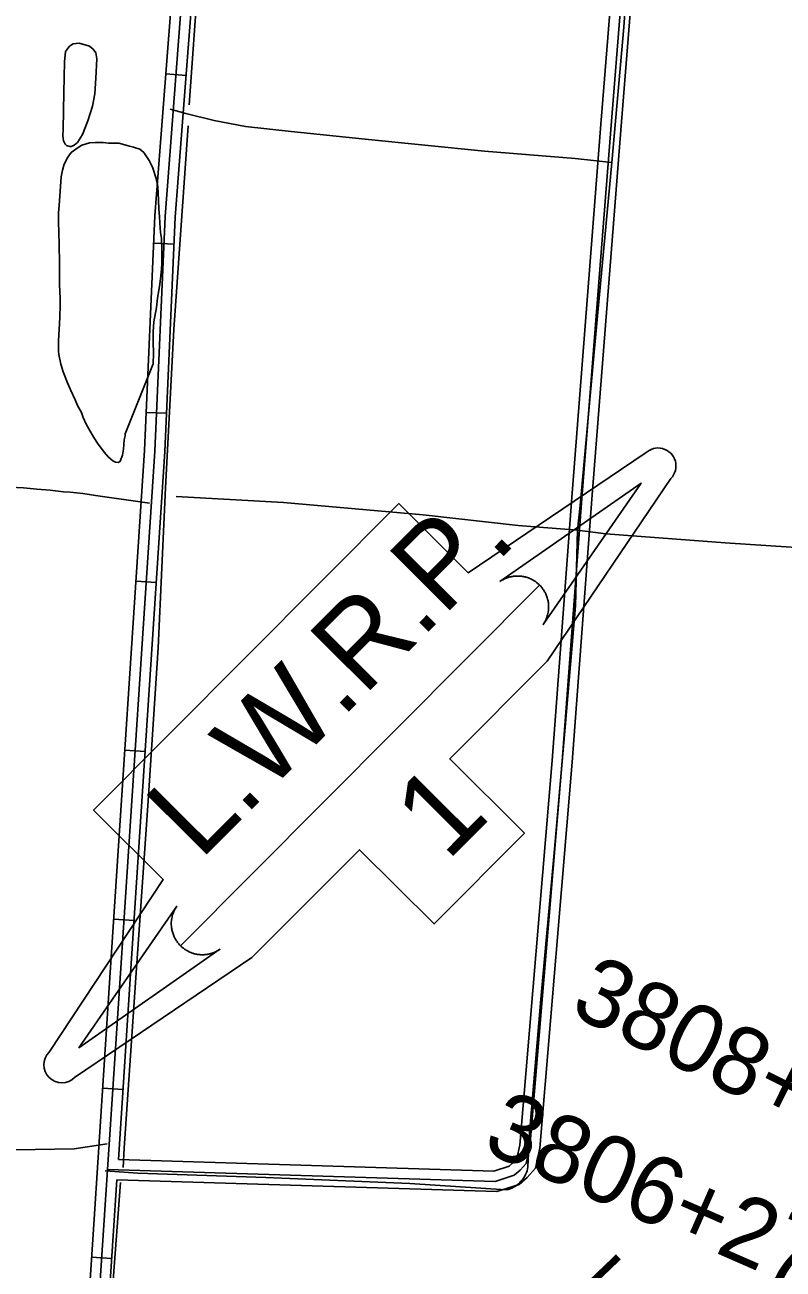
# Model space of a CAD drawing. Extents: x 3419139 to 3457078, y 540382 to 565875.
# Drawn here: x 3450003 to 3451122, y 549375 to 551211 of the extents above; entities that cross this region are included whole.
import ezdxf

# ---------------------------------------------------------------- set-up
doc = ezdxf.new("R2010")
doc.units = 0
for name, color, linetype in [('V-DTCH-CNTR', 7, 'Continuous'), ('V-RIVR-RANG-IDEN', 7, 'Continuous'), ('V-ROAD-CNTR', 7, 'Continuous'), ('V-SITE-VEGE', 7, 'Continuous'), ('V-SURV-IDEN', 7, 'Continuous'), ('V-TOPO-SHOR', 7, 'Continuous'), ('V-TOPO-WATR-IDEN', 7, 'Continuous')]:
    doc.layers.add(name, color=color, linetype=linetype)

msp = doc.modelspace()

# ---------------------------------------------------------------- linework, layer by layer
at = {"layer": 'V-DTCH-CNTR'}
for p, q in [((3450815.2, 551014.2), (3450869.2, 551008.3)), ((3450186.7, 550505.4), (3450107.2, 550516.6)), ((3450822.3, 550501.9), (3450818.5, 550465.6)), ((3450860.2, 550460.1), (3450818.5, 550465.6)), ((3450124.4, 549559.9), (3450075.5, 549552.1))]:
    msp.add_line(p, q, dxfattribs=at)
for points in [[(3450947.1, 551980.6), (3450930.6, 551824.6), (3450911.7, 551558), (3450886.9, 551208.2), (3450869.2, 551008.3)], [(3450217.6, 551087.1), (3450240.4, 551080.9), (3450282.3, 551070.4), (3450328.7, 551061.5), (3450396.2, 551053.9), (3450505.1, 551042.9), (3450681.5, 551025), (3450815.2, 551014.2)], [(3450869.2, 551008.3), (3450847.6, 550776.8), (3450828.9, 550572.3), (3450822.3, 550501.9)], [(3448834, 550578.8), (3449002.2, 550569.4), (3449267.6, 550554.5), (3449513.3, 550542.3), (3449732, 550531.6), (3449878.5, 550528.9), (3449888.8, 550529.8), (3449899.1, 550530.6), (3449909.4, 550531.1), (3449919.8, 550531.4), (3449930.1, 550531.4), (3449940.4, 550531.3), (3449950.7, 550530.9), (3449961, 550530.4), (3449980.9, 550529.3), (3450000.8, 550527.9), (3450020.6, 550526.3), (3450040.4, 550524.5), (3450060.2, 550522.4), (3450069.6, 550521.8), (3450079.1, 550520.9), (3450088.5, 550519.7), (3450097.9, 550518.3), (3450107.2, 550516.6)], [(3450818.5, 550465.6), (3450731.1, 550472.3), (3450590.8, 550488.3), (3450384.4, 550506.2), (3450226, 550515.4)], [(3450818.5, 550465.6), (3450815.6, 550353.7), (3450800.5, 550174.7), (3450784.7, 549994.5), (3450764.6, 549773.5), (3450747.6, 549575.5), (3450745.4, 549525.7)], [(3450860.2, 550460.1), (3451036.4, 550447), (3451193.8, 550436.4), (3451396.4, 550421.6), (3451557, 550407.1), (3451733.7, 550392.4), (3451936.6, 550376.9), (3452074.6, 550364.4), (3452246.1, 550345.2), (3452364.9, 550332.1)], [(3450075.5, 549552.1), (3449931.5, 549550.1), (3449720.3, 549554.1), (3449493.6, 549564), (3449287, 549571.2), (3449106.1, 549576.9), (3448895.9, 549584.8), (3448770, 549590.3)], [(3450745.4, 549525.7), (3450744.9, 549522.8), (3450744.1, 549520), (3450743.1, 549517.3), (3450742, 549514.6), (3450740.6, 549512), (3450739.1, 549509.5), (3450737.4, 549507.1), (3450735.6, 549504.9), (3450733.6, 549502.7), (3450731.5, 549500.7), (3450729.2, 549498.9), (3450726.8, 549497.3), (3450724.3, 549495.8), (3450721.7, 549494.4), (3450719, 549493.3), (3450716.3, 549492.4), (3450713.4, 549491.6)], [(3450713.4, 549491.6), (3450571.3, 549501.2), (3450358.8, 549510.1), (3450169.7, 549516.3), (3450121.5, 549519.8)]]:
    msp.add_lwpolyline(points, dxfattribs=at)
at = {"layer": 'V-ROAD-CNTR'}
for p, q in [((3450210.9, 551139), (3450240.8, 551136.7)), ((3450193.1, 550889.2), (3450223.1, 550887.8)), ((3450182.1, 550639.4), (3450212.1, 550638.1)), ((3450167, 550390.2), (3450196.9, 550388.2)), ((3450150.6, 550140.7), (3450180.5, 550138.8)), ((3450134.2, 549891.3), (3450164.1, 549889.3)), ((3450117.8, 549641.8), (3450147.7, 549639.9)), ((3450101.3, 549392.4), (3450131.3, 549390.4))]:
    msp.add_line(p, q, dxfattribs=at)
for points in [[(3450123.4, 547860.7), (3450027.9, 548203.3), (3450021, 548228), (3450019.2, 548252.4), (3450020.1, 548277.5), (3450031.6, 548342), (3450049.1, 548425.9), (3450083.2, 548889.6), (3450118.5, 549424.9), (3450144, 549811.7), (3450194.7, 550582.4), (3450209.9, 550928.6), (3450249.6, 551447), (3450280.4, 552016), (3450285.2, 552111.3)], [(3450140.9, 549536.4), (3450158.9, 549810.7), (3450209.6, 550581.6), (3450224.8, 550927.7), (3450264.5, 551446), (3450295.3, 552015.2), (3450299.5, 552095.7)], [(3450928.8, 551968.4), (3450913.8, 551822.7), (3450852.5, 551058.4), (3450810, 550513.6), (3450781, 550125.6), (3450733.2, 549557.6), (3450728.9, 549537.9), (3450723.2, 549531.5), (3450717.5, 549526.6), (3450695, 549519.3), (3450140.9, 549536.4)], [(3450957.6, 551955.3), (3450943.6, 551819.9), (3450882.4, 551056), (3450839.9, 550511.3), (3450810.9, 550123.3), (3450762.9, 549553.1), (3450756.5, 549523.7), (3450744.2, 549510), (3450732.4, 549499.9), (3450699.3, 549489.1), (3450138.9, 549506.5)], [(3450928.7, 551821.3), (3450867.5, 551057.2), (3450825, 550512.5), (3450796, 550124.4), (3450748, 549555.4), (3450742.7, 549530.8), (3450733.7, 549520.7), (3450725, 549513.3), (3450697.1, 549504.2), (3450124.9, 549521.9)], [(3450064.4, 548838.5), (3450068.2, 548890.7), (3450103.6, 549425.9), (3450129, 549812.7), (3450179.7, 550583.3), (3450194.9, 550929.5), (3450230, 551387.9)], [(3450137.9, 547864.7), (3450042.3, 548207.3), (3450035.8, 548230.6), (3450034.2, 548252.6), (3450035.1, 548275.9), (3450046.4, 548339.2), (3450064, 548423.8), (3450098.2, 548888.6), (3450133.5, 549423.9), (3450138.9, 549506.5)]]:
    msp.add_lwpolyline(points, dxfattribs=at)
at = {"layer": 'V-SITE-VEGE'}
msp.add_lwpolyline([(3450192.4, 550711), (3450150.8, 550608), (3450150.8, 550605), (3450149.7, 550599), (3450148.3, 550585.1), (3450146.8, 550576.2), (3450143.5, 550567.2), (3450140.9, 550565.7), (3450136.7, 550566), (3450132.6, 550567.9), (3450126.6, 550573.5), (3450119.9, 550580.9), (3450110.1, 550594), (3450104.8, 550602.6), (3450097.3, 550615.3), (3450093.5, 550622), (3450089, 550632.1), (3450086.4, 550639.2), (3450080.7, 550649.6), (3450077.3, 550658.2), (3450070.9, 550671.7), (3450066, 550682.9), (3450059.6, 550699.3), (3450056.2, 550710.5), (3450053.2, 550725.1), (3450052.8, 550730), (3450052.7, 550744.2), (3450053.1, 550754.3), (3450054.1, 550769.6), (3450054.5, 550780.9), (3450055.2, 550796.6), (3450055.1, 550807.8), (3450054.3, 550828), (3450054.3, 550840), (3450053.9, 550857.9), (3450053.8, 550889.4), (3450053, 550902.8), (3450052.5, 550922.6), (3450052.5, 550934.2), (3450053.6, 550944.7), (3450056.4, 550987), (3450058.3, 550997.1), (3450060.8, 551005.7), (3450066.4, 551016.2), (3450071.3, 551023), (3450080.2, 551029.4), (3450086.9, 551033.9), (3450098.5, 551037.6), (3450107.1, 551038.1), (3450118.7, 551038.1), (3450126.6, 551037), (3450132.9, 551037), (3450141.6, 551036.7), (3450157.3, 551032.2), (3450163.3, 551030.8), (3450172.6, 551027.8), (3450178.3, 551023.3), (3450186.5, 551011.4), (3450191.4, 551001.3), (3450196.7, 550984.8), (3450199, 550972.9), (3450200.2, 550952.7), (3450200.6, 550939.6), (3450201.8, 550928.4), (3450202.2, 550918.7), (3450203.3, 550905.2), (3450204.5, 550896.2), (3450204.9, 550881.6), (3450205, 550859.6), (3450204.6, 550850.9), (3450203.2, 550836.7), (3450201.4, 550825.5), (3450198.8, 550808.3), (3450197, 550794.1), (3450193.3, 550773.1), (3450192.2, 550758.5), (3450192.3, 550743.2), (3450192.7, 550727.1)], close=True, dxfattribs=at)
at = {"layer": 'V-TOPO-SHOR'}
for points in [[(3450309.6, 552087.8), (3450294.3, 551793), (3450275.8, 551527.7), (3450258.8, 551279.3), (3450245.5, 551093.7)], [(3450059.7, 551057.7), (3450060.3, 551111.7), (3450061.4, 551157.1), (3450062.9, 551172.1), (3450068.8, 551180), (3450074.3, 551183.5), (3450083, 551184.4), (3450098.3, 551180.1), (3450103.5, 551175.4), (3450107.8, 551170.2), (3450109.1, 551161.6), (3450107.6, 551132.8), (3450106.1, 551109.5), (3450102.6, 551091.4), (3450095.9, 551069.7), (3450088.1, 551049.5), (3450080.7, 551038.1), (3450075.6, 551034.1), (3450071.6, 551032.1), (3450069.3, 551032.1), (3450064.5, 551033.3), (3450062.2, 551035.2), (3450060.2, 551040.4), (3450059, 551047.9), (3450059.7, 551057.7)], [(3450244, 551062.6), (3450222.8, 550761.7), (3450210.3, 550528.1), (3450199.7, 550291.9), (3450184.7, 550065.8), (3450167.3, 549811.9), (3450149.4, 549553.1), (3450148, 549524.9)], [(3450144.3, 549502.6), (3450122.9, 549220.8), (3450106.8, 548970.8)]]:
    msp.add_lwpolyline(points, dxfattribs=at)
at = {"layer": 'V-TOPO-WATR-IDEN'}
msp.add_line((3450232.6, 549852.2), (3450762.5, 550384.6), dxfattribs=at)
for points in [[(3450038.8, 549695.1), (3450207, 549950.1), (3450104.4, 550052.2), (3450554.8, 550504.8), (3450657.4, 550402.7), (3450918.6, 550579.1)], [(3450956.2, 550541.7), (3450773.6, 550272.1), (3450630.1, 550128), (3450740.2, 550018.4), (3450606.8, 549884.4), (3450496.7, 549993.9), (3450338.1, 549834.6), (3450076.4, 549657.7)]]:
    msp.add_lwpolyline(points, dxfattribs=at)
for points in [[(3450704.1, 550389.8), (3450912.3, 550535.2), (3450767.9, 550326.3), (3450770.3, 550330.2), (3450772.2, 550334.1), (3450772.9, 550335.8), (3450773.4, 550337.2), (3450774, 550339), (3450774.5, 550340.8), (3450774.9, 550342.4), (3450775.3, 550344.5), (3450775.6, 550346.8), (3450775.7, 550348.1), (3450775.9, 550349.8), (3450775.9, 550352), (3450775.9, 550353.7), (3450775.8, 550355.5), (3450775.7, 550356.8), (3450775.5, 550358.1), (3450775.3, 550359.7), (3450775, 550361.2), (3450774.7, 550362.7), (3450774.4, 550363.9), (3450773.9, 550365.6), (3450773.4, 550367.3), (3450772.9, 550368.6), (3450772.3, 550370.1), (3450771.7, 550371.4), (3450771.1, 550372.6), (3450770.7, 550373.5), (3450770, 550374.8), (3450769.2, 550376.1), (3450768.4, 550377.4), (3450767.5, 550378.6), (3450766.7, 550379.7), (3450765.8, 550380.9), (3450765, 550381.8), (3450763.8, 550383.2), (3450762.5, 550384.6), (3450762, 550385), (3450761.3, 550385.7), (3450760.5, 550386.4), (3450759.7, 550387.1), (3450758.9, 550387.8), (3450758.1, 550388.4), (3450757.2, 550389.1), (3450756.5, 550389.6), (3450755.5, 550390.3), (3450754.5, 550390.9), (3450753.9, 550391.3), (3450752.1, 550392.3), (3450751.2, 550392.8), (3450750.5, 550393.2), (3450749.4, 550393.7), (3450748.4, 550394.1), (3450747.4, 550394.6), (3450746.1, 550395.1), (3450744.9, 550395.5), (3450744, 550395.8), (3450743.2, 550396), (3450742.1, 550396.4), (3450741.1, 550396.6), (3450739.9, 550396.9), (3450738.7, 550397.1), (3450737.5, 550397.3), (3450736, 550397.6), (3450734.9, 550397.7), (3450733.7, 550397.8), (3450732.5, 550397.9), (3450731.5, 550397.9), (3450730.4, 550397.9), (3450728.9, 550397.9), (3450728.8, 550397.9), (3450727.9, 550397.9), (3450727.2, 550397.8), (3450726.1, 550397.7), (3450724.9, 550397.6), (3450723.9, 550397.5), (3450722.9, 550397.3), (3450721.8, 550397.1), (3450720.7, 550396.9), (3450719.9, 550396.7), (3450718.8, 550396.5), (3450717.4, 550396.1), (3450716.6, 550395.9), (3450716, 550395.7), (3450715.4, 550395.5), (3450714.7, 550395.2), (3450713.7, 550394.9), (3450712.8, 550394.5), (3450711.9, 550394.1), (3450711.1, 550393.7), (3450709.9, 550393.2), (3450709.3, 550392.9), (3450708.2, 550392.3), (3450707, 550391.6), (3450706.1, 550391.1), (3450705.5, 550390.7), (3450704.8, 550390.3), (3450704.4, 550390)], [(3450290.9, 549847), (3450082.7, 549701.6), (3450227.1, 549910.5), (3450224.7, 549906.6), (3450222.8, 549902.6), (3450222.1, 549901), (3450221.6, 549899.5), (3450221, 549897.7), (3450220.5, 549895.9), (3450220.1, 549894.4), (3450219.7, 549892.3), (3450219.4, 549890), (3450219.3, 549888.7), (3450219.1, 549887), (3450219.1, 549884.8), (3450219.1, 549883.1), (3450219.2, 549881.2), (3450219.3, 549880), (3450219.5, 549878.7), (3450219.7, 549877), (3450220, 549875.6), (3450220.3, 549874.1), (3450220.6, 549872.9), (3450221.1, 549871.1), (3450221.6, 549869.5), (3450222.1, 549868.2), (3450222.7, 549866.6), (3450223.3, 549865.3), (3450223.9, 549864.2), (3450224.3, 549863.3), (3450225.1, 549862), (3450225.8, 549860.6), (3450226.6, 549859.4), (3450227.5, 549858.2), (3450228.3, 549857.1), (3450229.2, 549855.9), (3450230, 549854.9), (3450231.2, 549853.6), (3450232.6, 549852.2), (3450233, 549851.7), (3450233.7, 549851.1), (3450234.5, 549850.3), (3450235.3, 549849.6), (3450236.1, 549849), (3450236.9, 549848.3), (3450237.8, 549847.6), (3450238.5, 549847.1), (3450239.5, 549846.5), (3450240.5, 549845.8), (3450241.1, 549845.4), (3450242.9, 549844.4), (3450243.8, 549843.9), (3450244.5, 549843.6), (3450245.6, 549843.1), (3450246.6, 549842.6), (3450247.7, 549842.2), (3450248.9, 549841.7), (3450250.1, 549841.3), (3450251, 549841), (3450251.8, 549840.7), (3450252.9, 549840.4), (3450253.9, 549840.1), (3450255.1, 549839.9), (3450256.3, 549839.6), (3450257.5, 549839.4), (3450259, 549839.2), (3450260.1, 549839.1), (3450261.3, 549839), (3450262.5, 549838.9), (3450263.5, 549838.8), (3450264.6, 549838.8), (3450266.1, 549838.8), (3450266.2, 549838.8), (3450267.1, 549838.9), (3450267.8, 549838.9), (3450268.9, 549839), (3450270.1, 549839.1), (3450271.2, 549839.3), (3450272.1, 549839.4), (3450273.2, 549839.6), (3450274.3, 549839.8), (3450275.1, 549840), (3450276.2, 549840.3), (3450277.6, 549840.6), (3450278.4, 549840.9), (3450279.1, 549841.1), (3450279.6, 549841.3), (3450280.4, 549841.5), (3450281.3, 549841.9), (3450282.2, 549842.2), (3450283.1, 549842.6), (3450284, 549843), (3450285.1, 549843.6), (3450285.7, 549843.9), (3450286.8, 549844.5), (3450288, 549845.1), (3450288.9, 549845.7), (3450289.6, 549846.1), (3450290.2, 549846.5), (3450290.6, 549846.8)]]:
    msp.add_lwpolyline(points, close=True, dxfattribs=at)
for centre, start, end in [((3450937.4, 550560.4), 315.1375, 135.1375), ((3450057.6, 549676.4), 135.1375, 315.1375)]:
    msp.add_arc(centre, 26.5, start, end, dxfattribs=at)

# ---------------------------------------------------------------- texts
at = {"layer": 'V-RIVR-RANG-IDEN'}
msp.add_text('U-110', height=83, rotation=313.7436, dxfattribs=at).set_placement((3450809.5, 549345.4))
at = {"layer": 'V-SURV-IDEN'}
for s, rotation, p in [('3808+66.6', 333.7202, (3450804.4, 549752.8)), ('3806+27.5', 336.3638, (3450675.5, 549550.6))]:
    msp.add_text(s, height=100, rotation=rotation, dxfattribs=at).set_placement(p)
at = {"layer": 'V-TOPO-WATR-IDEN'}
for s, rotation, p in [('L.W.R.P.', 45.1375, (3450261.7, 549977.1)), ('1', 45.1376, (3450626.1, 549975.4))]:
    msp.add_text(s, height=124.5, rotation=rotation, dxfattribs=at).set_placement(p)

doc.saveas('drawing.dxf')
